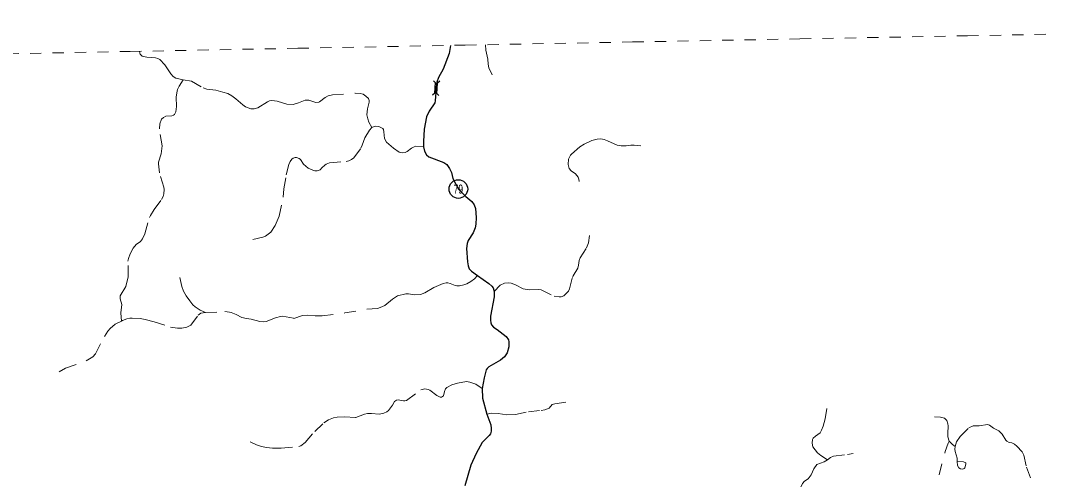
# Model space of a CAD drawing. Extents: x 220.8 to 246.7, y 7287.6 to 7315.8.
# Drawn here: x 230.23 to 239.4, y 7311.69 to 7315.78 of the extents above; entities that cross this region are included whole.
import ezdxf
from ezdxf.enums import TextEntityAlignment as Align

# ---------------------------------------------------------------- set-up
doc = ezdxf.new("R2010")
doc.units = 0
doc.header["$LTSCALE"] = 0.032
for name, pattern in [('DOTTED', [1.5, 0.3, -1.2]), ('LONG_DASHED', [7.5, 6, -1.5]), ('MEDIUM_DASHED', [4.5, 3, -1.5]), ('SHORT_DASHED', [2.7, 1.5, -1.2])]:
    doc.linetypes.add(name, pattern=pattern)
for name, color, linetype, lineweight in [('10', 7, 'Continuous', 25), ('13', 7, 'Continuous', 25), ('35', 7, 'SHORT_DASHED', 13), ('4', 7, 'LONG_DASHED', 25), ('6', 7, 'MEDIUM_DASHED', 13), ('7', 7, 'DOTTED', 13)]:
    doc.layers.add(name, color=color, linetype=linetype, lineweight=lineweight)
doc.layers.add('61', color=7, linetype='Continuous')

msp = doc.modelspace()

# ---------------------------------------------------------------- linework, layer by layer
at = {"layer": '10'}
for p, q in [((233.948, 7315.1326), (233.9538, 7315.2249)), ((233.9725, 7315.2415), (233.9538, 7315.2249)), ((233.928, 7315.1338), (233.9093, 7315.1175)), ((233.9645, 7315.114), (233.948, 7315.1326))]:
    msp.add_line(p, q, dxfattribs=at)
msp.add_lwpolyline([(233.928, 7315.1338), (233.9338, 7315.2261), (233.9173, 7315.2449)], dxfattribs=at)
at = {"layer": '13'}
msp.add_circle((234.1393, 7314.2788), 0.083, dxfattribs=at)
at = {"layer": '35'}
msp.add_lwpolyline([(220.7543, 7315.3049), (222.2482, 7315.3343), (223.7422, 7315.3636), (225.2361, 7315.3926), (226.7301, 7315.4216), (228.224, 7315.4503), (229.718, 7315.4789), (231.2119, 7315.5074), (232.7059, 7315.5357), (234.1998, 7315.5638), (235.6938, 7315.5918), (237.1877, 7315.6196), (238.6817, 7315.6472), (240.1757, 7315.6748), (241.6697, 7315.7021), (243.1636, 7315.7293), (244.6576, 7315.7563), (246.1516, 7315.7832)], dxfattribs=at)
at = {"layer": '4'}
msp.add_lwpolyline([(234.0682, 7315.5613), (234.0582, 7315.4893), (234.0033, 7315.3495), (233.9633, 7315.2746), (233.9477, 7315.2336), (233.9431, 7315.2179), (233.9402, 7315.1793), (233.9334, 7315.0662), (233.9284, 7315.0475), (233.8785, 7314.9751), (233.856, 7314.9227), (233.8352, 7314.8147), (233.8273, 7314.7031), (233.828, 7314.657), (233.8385, 7314.6182), (233.8548, 7314.5833), (233.876, 7314.5658), (234.0083, 7314.5159), (234.037, 7314.4971), (234.0594, 7314.4635), (234.0781, 7314.426), (234.0894, 7314.3736), (234.1393, 7314.2788), (234.2067, 7314.2114), (234.2591, 7314.1664), (234.2816, 7314.139), (234.2928, 7314.1053), (234.299, 7314.0254), (234.2965, 7313.9655), (234.2903, 7313.9331), (234.2716, 7313.8869), (234.2266, 7313.8195), (234.2167, 7313.7921), (234.2129, 7313.7471), (234.2217, 7313.6286), (234.2266, 7313.5924), (234.2366, 7313.5662), (234.2566, 7313.5462), (234.3098, 7313.5082), (234.4126, 7313.4352), (234.4375, 7313.4115), (234.4488, 7313.3977), (234.4601, 7313.3644), (234.4575, 7313.3154), (234.4263, 7313.1432), (234.4251, 7313.107), (234.4288, 7313.0845), (234.4363, 7313.0658), (234.4513, 7313.0458), (234.485, 7313.0258), (234.5648, 7312.961), (234.5861, 7312.9335), (234.591, 7312.9148), (234.5885, 7312.8711), (234.5761, 7312.8149), (234.5524, 7312.7813), (234.5162, 7312.7513), (234.4113, 7312.6914), (234.3951, 7312.6764), (234.3876, 7312.6639), (234.3689, 7312.5928), (234.3502, 7312.4983), (234.3552, 7312.4119), (234.3934, 7312.2675), (234.4288, 7312.1723), (234.4326, 7312.1411), (234.4313, 7312.1174), (234.4251, 7312.0924), (234.4151, 7312.0787), (234.3527, 7312.015), (234.299, 7311.9177), (234.2504, 7311.8129), (234.1692, 7311.5258)], dxfattribs=at)
at = {"layer": '6'}
for points in [[(234.3802, 7315.5672), (234.3853, 7315.5192), (234.4017, 7315.4395), (234.4042, 7315.3952), (234.4106, 7315.3623), (234.4397, 7315.299)], [(231.2937, 7315.509), (231.2956, 7315.4932), (231.3004, 7315.4836), (231.3185, 7315.4665), (231.3605, 7315.455), (231.4368, 7315.4493), (231.4578, 7315.4436), (231.475, 7315.435), (231.5208, 7315.3892), (231.5723, 7315.3081), (231.5951, 7315.2827), (231.6172, 7315.2686), (231.6834, 7315.2538)], [(231.1332, 7313.1), (231.1269, 7313.1725), (231.1353, 7313.2485), (231.1205, 7313.2992), (231.1218, 7313.3263), (231.171, 7313.4097), (231.1936, 7313.4958), (231.1906, 7313.6339), (231.1951, 7313.6581), (231.2102, 7313.6996), (231.2389, 7313.7502), (231.2653, 7313.7841), (231.3023, 7313.8113), (231.3212, 7313.8332), (231.3423, 7313.88), (231.3831, 7314.0234), (231.3914, 7314.0415), (231.4238, 7314.0959), (231.491, 7314.1849), (231.5053, 7314.2121), (231.5121, 7314.2355), (231.5136, 7314.274), (231.5099, 7314.2951), (231.4714, 7314.4242), (231.4623, 7314.5035), (231.4638, 7314.5186), (231.488, 7314.5918), (231.4948, 7314.6658), (231.4714, 7314.8167), (231.4751, 7314.8605), (231.491, 7314.9028), (231.5068, 7314.9186), (231.528, 7314.9284), (231.5838, 7314.9337), (231.5959, 7314.9382), (231.605, 7314.9443), (231.6186, 7314.9677), (231.6246, 7315.016), (231.6201, 7315.0983), (231.6261, 7315.1368), (231.6344, 7315.167), (231.648, 7315.1964), (231.6834, 7315.2538)], [(231.6834, 7315.2538), (231.7587, 7315.2411), (231.8633, 7315.1814), (231.8942, 7315.1693), (231.974, 7315.1606), (232.037, 7315.1452), (232.0826, 7315.1304), (232.1181, 7315.1097), (232.155, 7315.0828), (232.2147, 7315.0299), (232.2388, 7315.0124), (232.2884, 7314.9936), (232.3173, 7314.9936), (232.3501, 7315.0037), (232.4366, 7315.058), (232.4541, 7315.0661), (232.4742, 7315.0694), (232.5211, 7315.062), (232.609, 7315.0372), (232.664, 7315.0339), (232.7122, 7315.0486), (232.7733, 7315.0728), (232.8054, 7315.0728), (232.8678, 7315.0513), (232.8933, 7315.0547), (232.9013, 7315.058), (232.9509, 7315.0976), (232.9784, 7315.1103), (233.016, 7315.1197), (233.2192, 7315.1351), (233.2628, 7315.1325), (233.2902, 7315.1251), (233.3144, 7315.109), (233.3365, 7315.0862), (233.3439, 7315.0694), (233.3446, 7315.054), (233.3291, 7314.9963), (233.3224, 7314.9427), (233.3305, 7314.9058), (233.3412, 7314.877), (233.3667, 7314.8287)], [(232.3066, 7313.827), (232.3949, 7313.8491), (232.4185, 7313.8585), (232.4651, 7313.8932), (232.5053, 7313.9524), (232.5416, 7314.0376), (232.5755, 7314.2055), (232.5826, 7314.2797), (232.6039, 7314.4058), (232.6259, 7314.4973), (232.6386, 7314.5241), (232.6535, 7314.5462), (232.6662, 7314.5557), (232.6827, 7314.5604), (232.6946, 7314.5612), (232.7174, 7314.5517), (232.7293, 7314.5431), (232.7569, 7314.5005), (232.7987, 7314.4666), (232.8405, 7314.4461), (232.8594, 7314.4413), (232.8791, 7314.4405), (232.9075, 7314.4508), (232.9201, 7314.4674), (232.9469, 7314.4918), (232.9587, 7314.5005), (232.9895, 7314.5139), (233.137, 7314.5241), (233.1606, 7314.5312), (233.1843, 7314.5415), (233.2056, 7314.5581), (233.2679, 7314.6432), (233.2821, 7314.67), (233.305, 7314.7371), (233.346, 7314.8041), (233.3667, 7314.8287)], [(233.3667, 7314.8287), (233.3875, 7314.8381), (233.4022, 7314.8408), (233.4291, 7314.8361), (233.4653, 7314.8206), (233.4713, 7314.8106), (233.4753, 7314.7885), (233.4807, 7314.7288), (233.4974, 7314.6966), (233.5591, 7314.643), (233.6114, 7314.6067), (233.6409, 7314.6007), (233.6651, 7314.6054), (233.6812, 7314.6134), (233.7201, 7314.643), (233.7435, 7314.6564), (233.7596, 7314.6617), (233.828, 7314.657)], [(234.4601, 7313.3644), (234.5118, 7313.4201), (234.5518, 7313.438), (234.5854, 7313.4415), (234.611, 7313.438), (234.6481, 7313.4247), (234.7177, 7313.3876), (234.7728, 7313.3783), (234.8569, 7313.3806), (234.8767, 7313.3777), (234.995, 7313.3214), (235.0391, 7313.3156), (235.0565, 7313.3174), (235.0809, 7313.3255), (235.1221, 7313.3678), (235.1308, 7313.3864), (235.1563, 7313.4879), (235.1633, 7313.5053), (235.2062, 7313.5738), (235.2126, 7313.5999), (235.2172, 7313.6399), (235.2248, 7313.6643), (235.2839, 7313.7542), (235.3013, 7313.7983), (235.3095, 7313.8627)], [(231.1332, 7313.1), (231.1436, 7313.1052), (231.1809, 7313.1191), (231.2071, 7313.125), (231.229, 7313.1271), (231.3013, 7313.122), (231.3437, 7313.114), (231.424, 7313.0921), (231.5692, 7313.0468), (231.6335, 7313.0366), (231.6722, 7313.0373), (231.716, 7313.0454), (231.7518, 7313.0644), (231.8167, 7313.1512), (231.8284, 7313.1615), (231.8401, 7313.1702), (231.8834, 7313.1766), (232.0555, 7313.1841), (232.0956, 7313.1797), (232.1131, 7313.1768), (232.1569, 7313.1593), (232.2073, 7313.1323), (232.2489, 7313.1228), (232.2891, 7313.1177), (232.3672, 7313.0972), (232.3971, 7313.0928), (232.4234, 7313.0972), (232.5081, 7313.1293), (232.5519, 7313.1417), (232.5687, 7313.1432), (232.6716, 7313.1242), (232.7497, 7313.1498), (232.7928, 7313.152), (232.8614, 7313.1454), (232.9227, 7313.1476), (233.1272, 7313.1724), (233.3235, 7313.2053), (233.4162, 7313.2126), (233.4411, 7313.2199), (233.4827, 7313.2396), (233.552, 7313.2958), (233.5966, 7313.3257), (233.6696, 7313.3418), (233.6951, 7313.3425), (233.7499, 7313.333), (233.8017, 7313.3367), (233.8404, 7313.3513), (233.92, 7313.3987), (234.0039, 7313.4367), (234.0309, 7313.4411), (234.0448, 7313.4403), (234.0653, 7313.4359), (234.112, 7313.4177), (234.1266, 7313.4155), (234.1492, 7313.4148), (234.1886, 7313.4221), (234.2156, 7313.4323), (234.2507, 7313.4535), (234.2821, 7313.4768), (234.3098, 7313.5082)], [(230.5771, 7312.6475), (230.6341, 7312.6782), (230.8195, 7312.7439), (230.8779, 7312.7796), (230.9005, 7312.8081), (230.9823, 7312.9629), (231.0115, 7313.0089), (231.0319, 7313.033), (231.0772, 7313.0717), (231.1332, 7313.1)], [(232.281, 7312.0218), (232.3385, 7311.9941), (232.3824, 7311.9789), (232.4274, 7311.97), (232.4813, 7311.9653), (232.5592, 7311.9643), (232.7167, 7311.9789), (232.7339, 7311.9857), (232.7726, 7312.0171), (232.8574, 7312.1149), (232.939, 7312.1908), (232.9808, 7312.219), (233.0247, 7312.2357), (233.0572, 7312.242), (233.122, 7312.2462), (233.2245, 7312.2399), (233.303, 7312.2692), (233.3292, 7312.2734), (233.3647, 7312.2745), (233.4327, 7312.2692), (233.4735, 7312.2776), (233.4997, 7312.2891), (233.5164, 7312.3027), (233.552, 7312.3487), (233.5687, 7312.3822), (233.5865, 7312.3937), (233.6022, 7312.3979), (233.6482, 7312.3874), (233.6629, 7312.3874), (233.6754, 7312.3916), (233.8051, 7312.4858), (233.8407, 7312.4941), (233.871, 7312.4889), (233.8846, 7312.4826), (233.9474, 7312.4345), (233.9777, 7312.4209), (233.9893, 7312.4209), (233.9987, 7312.4251), (234.006, 7312.4335), (234.0154, 7312.4711), (234.0259, 7312.4941), (234.0374, 7312.5077), (234.0803, 7312.5297), (234.1315, 7312.5464), (234.2131, 7312.56), (234.2424, 7312.5548), (234.2937, 7312.536), (234.3502, 7312.4983)]]:
    msp.add_lwpolyline(points, dxfattribs=at)
at = {"layer": '7'}
for points in [[(235.2163, 7314.3451), (235.2133, 7314.3675), (235.2073, 7314.384), (235.1848, 7314.4139), (235.1458, 7314.4402), (235.1293, 7314.4611), (235.1203, 7314.4971), (235.1233, 7314.5443), (235.1391, 7314.5818), (235.1473, 7314.59), (235.2238, 7314.6552), (235.2605, 7314.6785), (235.3294, 7314.7115), (235.3767, 7314.7242), (235.4096, 7314.7264), (235.4389, 7314.7212), (235.4696, 7314.7107), (235.555, 7314.6702), (235.5925, 7314.665), (235.636, 7314.665), (235.6794, 7314.671), (235.7079, 7314.671), (235.7664, 7314.665)], [(231.6548, 7313.4899), (231.6717, 7313.4089), (231.6868, 7313.3672), (231.7098, 7313.3243), (231.7424, 7313.2795), (231.7696, 7313.2463), (231.7908, 7313.2269), (231.8367, 7313.1985), (231.8834, 7313.1766)], [(234.3934, 7312.2675), (234.4346, 7312.2786), (234.4932, 7312.2754), (234.5716, 7312.2636), (234.6476, 7312.2659), (234.7648, 7312.2897), (234.8772, 7312.3016), (234.9105, 7312.3079), (234.9493, 7312.3237), (234.9762, 7312.3538), (234.9991, 7312.3625), (235.1179, 7312.3776)], [(237.4272, 7312.3196), (237.4119, 7312.2274), (237.3945, 7312.163), (237.3798, 7312.1247), (237.3667, 7312.1017), (237.3258, 7312.073), (237.3058, 7312.053), (237.2989, 7312.0412), (237.2954, 7312.0086), (237.3032, 7311.9773), (237.3445, 7311.9247), (237.3741, 7311.8999), (237.4328, 7311.8598)], [(238.3884, 7312.2456), (238.4411, 7312.2413), (238.478, 7312.2337), (238.4979, 7312.2116), (238.5077, 7312.1815), (238.509, 7312.1641), (238.5056, 7312.097), (238.5073, 7312.066), (238.52, 7312.0291)], [(238.5714, 7311.9803), (238.585, 7312.021), (238.6176, 7312.0707), (238.6949, 7312.1471), (238.7318, 7312.1653), (238.7853, 7312.1641), (238.8604, 7312.1764), (238.8787, 7312.17), (238.9135, 7312.145), (238.9623, 7312.1199), (238.9912, 7312.0911), (239.0251, 7312.0363), (239.0336, 7312.0282), (239.054, 7312.0155), (239.0769, 7312.0117), (239.1024, 7312.0011), (239.1232, 7311.9845), (239.1699, 7311.9319), (239.1847, 7311.9039), (239.2089, 7311.7952), (239.2509, 7311.6815)], [(238.4295, 7311.7272), (238.4821, 7311.9345), (238.5091, 7312.011), (238.52, 7312.0291)], [(238.52, 7312.0291), (238.5489, 7311.9973), (238.5714, 7311.9803)], [(237.4328, 7311.8598), (237.4606, 7311.8812), (237.4854, 7311.8933), (237.6116, 7311.9094), (237.6607, 7311.919)], [(238.5714, 7311.9803), (238.5696, 7311.9577), (238.5727, 7311.9351), (238.5898, 7311.8752), (238.5898, 7311.8466)], [(237.4328, 7311.8598), (237.4045, 7311.8433), (237.3393, 7311.8207), (237.311, 7311.7807), (237.2884, 7311.7272), (237.2619, 7311.6928), (237.2288, 7311.6693), (237.2101, 7311.6485), (237.1927, 7311.6106), (237.1788, 7311.5676), (237.1518, 7311.5184)]]:
    msp.add_lwpolyline(points, dxfattribs=at)
msp.add_lwpolyline([(238.5898, 7311.8466), (238.5935, 7311.811), (238.6045, 7311.7889), (238.6204, 7311.7804), (238.6393, 7311.7785), (238.6534, 7311.7834), (238.6589, 7311.7889), (238.6675, 7311.8232), (238.6662, 7311.8354), (238.6467, 7311.8446)], close=True, dxfattribs=at)

# ---------------------------------------------------------------- texts
at = {"layer": '61', "width": 0.7}
msp.add_text('79', height=0.08, dxfattribs=at).set_placement((234.1392, 7314.2388), align=Align.CENTER)

doc.saveas('drawing.dxf')
